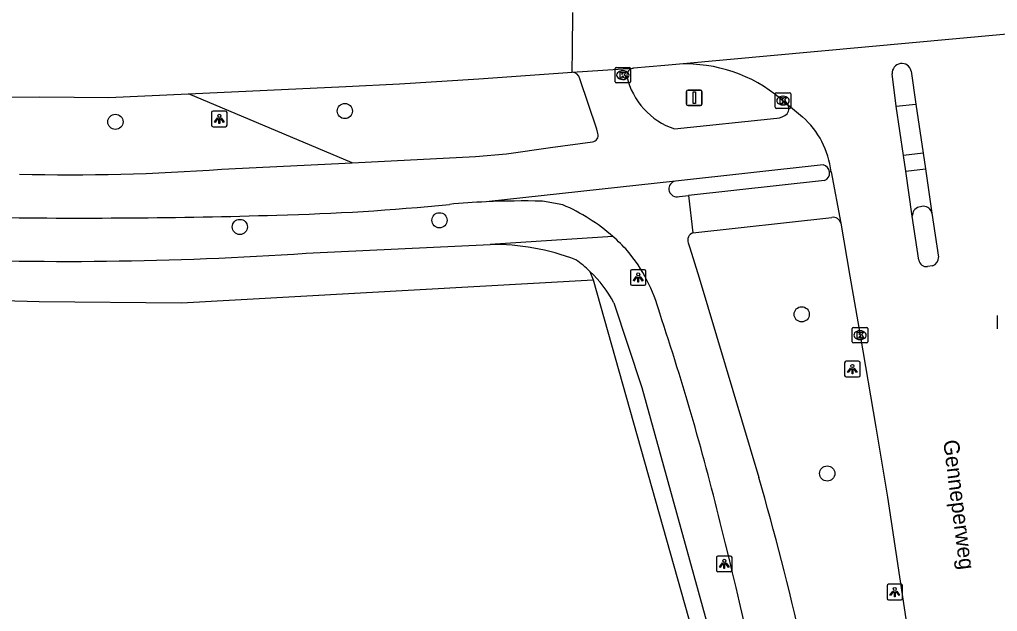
# Model space of a CAD drawing. Extents: x 160203 to 161526, y 379529 to 381797.
# Drawn here: x 160754.1 to 160816.9, y 380821.9 to 380859.9 of the extents above; entities that cross this region are included whole.
import ezdxf

# ---------------------------------------------------------------- set-up
doc = ezdxf.new("R2010")
doc.units = 0
for name, color, linetype in [('IMGEO_Berm_groen', 7, 'Continuous'), ('IMGEO_Boom', 7, 'Continuous'), ('IMGEO_Fietspad_open', 7, 'Continuous'), ('IMGEO_Grasland_agrarisch', 7, 'Continuous'), ('IMGEO_Hek', 7, 'Continuous'), ('IMGEO_Kolk', 7, 'Continuous'), ('IMGEO_Lichtpunt', 7, 'Continuous'), ('IMGEO_Openbare_ruimte_label', 7, 'Continuous'), ('IMGEO_Rijbaan_lokaal_gesloten', 7, 'Continuous'), ('IMGEO_Rijbaan_lokaal_open', 7, 'Continuous'), ('IMGEO_Verkeersbordpaal', 7, 'Continuous'), ('IMGEO_Voetpad_open', 7, 'Continuous')]:
    doc.layers.add(name, color=color, linetype=linetype)

msp = doc.modelspace()

# ---------------------------------------------------------------- linework, layer by layer
at = {"layer": 'IMGEO_Berm_groen'}
msp.add_lwpolyline([(160775.483, 380850.741), (160764.954, 380855.176)], dxfattribs=at)
at = {"layer": 'IMGEO_Boom'}
for centre in [(160775.008, 380854.065), (160760.26, 380853.371), (160768.259, 380846.611), (160781.086, 380847.039), (160804.366, 380840.994), (160806.008, 380830.763)]:
    msp.add_circle(centre, 0.489, dxfattribs=at)
at = {"layer": 'IMGEO_Fietspad_open'}
for points in [[(160791.275, 380852.614), (160791.205, 380852.905), (160790.104, 380856.13)], [(160810.441, 380854.37), (160811.699, 380854.505)], [(160796.186, 380852.912), (160802.764, 380853.61)], [(160775.483, 380850.741), (160783.41, 380851.131), (160785.393, 380851.307), (160788.226, 380851.722), (160790.924, 380852.076)], [(160812.162, 380851.362), (160810.902, 380851.209)], [(160767.104, 380850.329), (160775.483, 380850.741)], [(160805.738, 380850.598), (160796.255, 380849.562)], [(160806.25, 380850.156), (160806.159, 380850.144)]]:
    msp.add_lwpolyline(points, dxfattribs=at)
for centre, radius, start, end in [((160789.622, 380856.075), 0.485, 6.46696, 90.52993), ((160793.602, 380856.343), 0.479, 94.61403, 187.10993), ((160797.713, 380857.372), 4.715, 193.34725, 251.09856), ((160803.069, 380854.207), 0.478, 318.72664, 47.2899), ((160802.703, 380854.676), 1.068, 273.26806, 312.75369), ((160790.847, 380852.51), 0.44, 280.04651, 13.71132), ((160757.511, 380977.397), 127.43, 268.46675, 274.31751), ((160805.653, 380850.097), 0.508, 5.33471, 80.3456), ((160767.096, 380993.559), 146.229, 271.38388, 275.74179), ((160786.621, 380794.716), 53.571, 92.71443, 95.24266), ((160758.146, 381259.181), 411.998, 269.1062, 271.73614)]:
    msp.add_arc(centre, radius, start, end, dxfattribs=at)
at = {"layer": 'IMGEO_Grasland_agrarisch'}
msp.add_lwpolyline([(160790.757, 380843.757), (160790.967, 380843.218), (160797.794, 380818.979), (160800.72, 380802.882), (160803.667, 380782.861), (160807.097, 380750), (160808.197, 380741.734), (160810.001, 380733.144), (160811.746, 380725.723)], dxfattribs=at)
at = {"layer": 'IMGEO_Hek'}
msp.add_lwpolyline([(160724.662, 380842.651), (160726.668, 380842.596), (160727.305, 380842.579), (160755.37, 380841.813), (160764.499, 380841.725), (160790.967, 380843.218), (160797.794, 380818.979), (160800.72, 380802.882), (160803.667, 380782.861), (160807.097, 380750), (160808.197, 380741.734), (160810.001, 380733.144), (160811.746, 380725.723), (160812.287, 380716.603)], dxfattribs=at)
at = {"layer": 'IMGEO_Kolk'}
for p, q in [((160792.368, 380855.946), (160792.368, 380856.798)), ((160792.443, 380856.872), (160793.295, 380856.872)), ((160792.856, 380856.652), (160792.881, 380856.652)), ((160793.369, 380856.798), (160793.369, 380855.946)), ((160793.295, 380855.872), (160792.443, 380855.872)), ((160792.879, 380856.092), (160792.854, 380856.092)), ((160802.738, 380855.237), (160803.59, 380855.237)), ((160802.663, 380854.311), (160802.663, 380855.163)), ((160803.151, 380855.017), (160803.176, 380855.017)), ((160803.664, 380855.163), (160803.664, 380854.311)), ((160803.59, 380854.237), (160802.738, 380854.237)), ((160803.174, 380854.457), (160803.149, 380854.457)), ((160816.945, 380840.066), (160816.945, 380840.918)), ((160807.691, 380840.153), (160808.543, 380840.153)), ((160807.616, 380839.227), (160807.616, 380840.079)), ((160808.104, 380839.933), (160808.129, 380839.933)), ((160808.617, 380840.079), (160808.617, 380839.227)), ((160808.543, 380839.153), (160807.691, 380839.153)), ((160808.127, 380839.373), (160808.102, 380839.373))]:
    msp.add_line(p, q, dxfattribs=at)
for points in [[(160792.368, 380855.946), (160792.368, 380856.798)], [(160792.443, 380856.872), (160793.295, 380856.872)], [(160792.689, 380856.572), (160792.812, 380856.572), (160792.812, 380856.421), (160792.942, 380856.572), (160793.106, 380856.572), (160792.96, 380856.421), (160793.113, 380856.172), (160792.961, 380856.172), (160792.876, 380856.336), (160792.812, 380856.269), (160792.812, 380856.172), (160792.689, 380856.172), (160792.689, 380856.572)], [(160793.369, 380856.798), (160793.369, 380855.946)], [(160793.295, 380855.872), (160792.443, 380855.872)], [(160802.738, 380855.237), (160803.59, 380855.237)], [(160802.663, 380854.311), (160802.663, 380855.163)], [(160802.984, 380854.937), (160803.107, 380854.937), (160803.107, 380854.786), (160803.237, 380854.937), (160803.401, 380854.937), (160803.255, 380854.786), (160803.408, 380854.537), (160803.256, 380854.537), (160803.171, 380854.701), (160803.107, 380854.634), (160803.107, 380854.537), (160802.984, 380854.537), (160802.984, 380854.937)], [(160803.664, 380855.163), (160803.664, 380854.311)], [(160803.59, 380854.237), (160802.738, 380854.237)], [(160816.945, 380840.066), (160816.945, 380840.918)], [(160807.691, 380840.153), (160808.543, 380840.153)], [(160807.616, 380839.227), (160807.616, 380840.079)], [(160807.937, 380839.853), (160808.06, 380839.853), (160808.06, 380839.702), (160808.19, 380839.853), (160808.354, 380839.853), (160808.208, 380839.702), (160808.361, 380839.453), (160808.209, 380839.453), (160808.124, 380839.617), (160808.06, 380839.55), (160808.06, 380839.453), (160807.937, 380839.453), (160807.937, 380839.853)], [(160808.617, 380840.079), (160808.617, 380839.227)], [(160808.543, 380839.153), (160807.691, 380839.153)]]:
    msp.add_lwpolyline(points, dxfattribs=at)
for centre, start, end in [((160792.445, 380856.796), 91.55205, 178.44795), ((160792.445, 380856.796), 91.55205, 178.44795), ((160793.293, 380856.796), 1.55205, 88.44795), ((160793.293, 380856.796), 1.55205, 88.44795), ((160792.445, 380855.948), 181.55205, 268.44795), ((160792.445, 380855.948), 181.55205, 268.44795), ((160793.293, 380855.948), 271.55205, 358.44795), ((160793.293, 380855.948), 271.55205, 358.44795), ((160802.74, 380855.161), 91.55205, 178.44795), ((160802.74, 380855.161), 91.55205, 178.44795), ((160803.588, 380855.161), 1.55205, 88.44795), ((160803.588, 380855.161), 1.55205, 88.44795), ((160802.74, 380854.313), 181.55205, 268.44795), ((160802.74, 380854.313), 181.55205, 268.44795), ((160803.588, 380854.313), 271.55205, 358.44795), ((160803.588, 380854.313), 271.55205, 358.44795), ((160807.693, 380840.077), 91.55205, 178.44795), ((160807.693, 380840.077), 91.55205, 178.44795), ((160808.541, 380840.077), 1.55205, 88.44795), ((160808.541, 380840.077), 1.55205, 88.44795), ((160807.693, 380839.229), 181.55205, 268.44795), ((160807.693, 380839.229), 181.55205, 268.44795), ((160808.541, 380839.229), 271.55205, 358.44795), ((160808.541, 380839.229), 271.55205, 358.44795)]:
    msp.add_arc(centre, 0.0765, start, end, dxfattribs=at)
for centre, major_axis, ratio, start_param, end_param in [((160792.855, 380856.372), (-0.387, 0.002), 0.722429, 4.712389, 7.853982), ((160792.88, 380856.372), (-0.39, 0.002), 0.717154, 1.570796, 4.712389), ((160803.15, 380854.737), (-0.387, 0.002), 0.722429, 4.712389, 7.853982), ((160803.175, 380854.737), (-0.39, 0.002), 0.717154, 1.570796, 4.712389), ((160808.103, 380839.653), (-0.387, 0.002), 0.722429, 4.712389, 7.853982), ((160808.128, 380839.653), (-0.39, 0.002), 0.717154, 1.570796, 4.712389)]:
    msp.add_ellipse(centre, major_axis=major_axis, ratio=ratio, start_param=start_param, end_param=end_param, dxfattribs=at)
at = {"layer": 'IMGEO_Lichtpunt'}
for p, q in [((160766.44, 380853.959), (160766.44, 380853.152)), ((160766.44, 380853.959), (160766.44, 380853.152)), ((160767.342, 380854.054), (160766.534, 380854.054)), ((160767.342, 380854.054), (160766.534, 380854.054)), ((160767.436, 380853.152), (160767.436, 380853.959)), ((160767.436, 380853.152), (160767.436, 380853.959)), ((160766.534, 380853.058), (160767.342, 380853.058)), ((160766.534, 380853.058), (160767.342, 380853.058)), ((160793.362, 380843.762), (160793.362, 380842.955)), ((160793.362, 380843.762), (160793.362, 380842.955)), ((160794.264, 380843.857), (160793.456, 380843.857)), ((160794.264, 380843.857), (160793.456, 380843.857)), ((160794.358, 380842.955), (160794.358, 380843.762)), ((160794.358, 380842.955), (160794.358, 380843.762)), ((160793.456, 380842.861), (160794.264, 380842.861)), ((160793.456, 380842.861), (160794.264, 380842.861)), ((160807.124, 380837.877), (160807.124, 380837.07)), ((160807.124, 380837.877), (160807.124, 380837.07)), ((160808.026, 380837.972), (160807.218, 380837.972)), ((160808.026, 380837.972), (160807.218, 380837.972)), ((160808.12, 380837.07), (160808.12, 380837.877)), ((160808.12, 380837.07), (160808.12, 380837.877)), ((160807.218, 380836.976), (160808.026, 380836.976)), ((160807.218, 380836.976), (160808.026, 380836.976)), ((160798.892, 380825.35), (160798.892, 380824.543)), ((160798.892, 380825.35), (160798.892, 380824.543)), ((160799.794, 380825.445), (160798.986, 380825.445)), ((160799.794, 380825.445), (160798.986, 380825.445)), ((160799.888, 380824.543), (160799.888, 380825.35)), ((160799.888, 380824.543), (160799.888, 380825.35)), ((160798.986, 380824.449), (160799.794, 380824.449)), ((160798.986, 380824.449), (160799.794, 380824.449)), ((160809.849, 380823.541), (160809.849, 380822.734)), ((160809.849, 380823.541), (160809.849, 380822.734)), ((160810.751, 380823.636), (160809.943, 380823.636)), ((160810.751, 380823.636), (160809.943, 380823.636)), ((160810.845, 380822.734), (160810.845, 380823.541)), ((160810.845, 380822.734), (160810.845, 380823.541)), ((160809.943, 380822.64), (160810.751, 380822.64)), ((160809.943, 380822.64), (160810.751, 380822.64))]:
    msp.add_line(p, q, dxfattribs=at)
for points in [[(160766.814, 380853.623), (160766.853, 380853.595), (160766.665, 380853.333), (160766.627, 380853.36), (160766.814, 380853.623)], [(160766.916, 380853.575), (160766.963, 380853.575), (160766.963, 380853.253), (160766.916, 380853.253), (160766.916, 380853.575)], [(160767.026, 380853.595), (160767.064, 380853.622), (160767.251, 380853.36), (160767.212, 380853.332), (160767.026, 380853.595)], [(160793.736, 380843.426), (160793.775, 380843.398), (160793.587, 380843.136), (160793.549, 380843.163), (160793.736, 380843.426)], [(160793.838, 380843.378), (160793.885, 380843.378), (160793.885, 380843.056), (160793.838, 380843.056), (160793.838, 380843.378)], [(160793.948, 380843.398), (160793.986, 380843.425), (160794.173, 380843.163), (160794.134, 380843.135), (160793.948, 380843.398)], [(160807.498, 380837.541), (160807.537, 380837.513), (160807.349, 380837.251), (160807.311, 380837.278), (160807.498, 380837.541)], [(160807.6, 380837.493), (160807.647, 380837.493), (160807.647, 380837.171), (160807.6, 380837.171), (160807.6, 380837.493)], [(160807.71, 380837.513), (160807.748, 380837.54), (160807.935, 380837.278), (160807.896, 380837.25), (160807.71, 380837.513)], [(160799.266, 380825.014), (160799.305, 380824.986), (160799.117, 380824.724), (160799.079, 380824.751), (160799.266, 380825.014)], [(160799.368, 380824.966), (160799.415, 380824.966), (160799.415, 380824.644), (160799.368, 380824.644), (160799.368, 380824.966)], [(160799.478, 380824.986), (160799.516, 380825.013), (160799.703, 380824.751), (160799.664, 380824.723), (160799.478, 380824.986)], [(160810.223, 380823.205), (160810.262, 380823.177), (160810.074, 380822.915), (160810.036, 380822.942), (160810.223, 380823.205)], [(160810.325, 380823.157), (160810.372, 380823.157), (160810.372, 380822.835), (160810.325, 380822.835), (160810.325, 380823.157)], [(160810.435, 380823.177), (160810.473, 380823.204), (160810.66, 380822.942), (160810.621, 380822.914), (160810.435, 380823.177)]]:
    msp.add_lwpolyline(points, dxfattribs=at)
for centre in [(160766.939, 380853.757), (160793.861, 380843.56), (160807.623, 380837.675), (160799.391, 380825.148), (160810.348, 380823.339)]:
    msp.add_circle(centre, 0.0994, dxfattribs=at)
for centre, start, end in [((160766.534, 380853.959), 90, 180), ((160766.534, 380853.959), 90, 180), ((160767.342, 380853.959), 0, 90), ((160767.342, 380853.959), 0, 90), ((160766.534, 380853.152), 180, 270), ((160766.534, 380853.152), 180, 270), ((160767.342, 380853.152), 270, 0), ((160767.342, 380853.152), 270, 360), ((160793.456, 380843.762), 90, 180), ((160793.456, 380843.762), 90, 180), ((160794.264, 380843.762), 0, 90), ((160794.264, 380843.762), 0, 90), ((160793.456, 380842.955), 180, 270), ((160793.456, 380842.955), 180, 270), ((160794.264, 380842.955), 270, 0), ((160794.264, 380842.955), 270, 360), ((160807.218, 380837.877), 90, 180), ((160807.218, 380837.877), 90, 180), ((160808.026, 380837.877), 0, 90), ((160808.026, 380837.877), 0, 90), ((160807.218, 380837.07), 180, 270), ((160807.218, 380837.07), 180, 270), ((160808.026, 380837.07), 270, 0), ((160808.026, 380837.07), 270, 360), ((160798.986, 380825.35), 90, 180), ((160798.986, 380825.35), 90, 180), ((160799.794, 380825.35), 0, 90), ((160799.794, 380825.35), 0, 90), ((160798.986, 380824.543), 180, 270), ((160798.986, 380824.543), 180, 270), ((160799.794, 380824.543), 270, 0), ((160799.794, 380824.543), 270, 360), ((160809.943, 380823.541), 90, 180), ((160809.943, 380823.541), 90, 180), ((160810.751, 380823.541), 0, 90), ((160810.751, 380823.541), 0, 90), ((160809.943, 380822.734), 180, 270), ((160809.943, 380822.734), 180, 270), ((160810.751, 380822.734), 270, 0), ((160810.751, 380822.734), 270, 360)]:
    msp.add_arc(centre, 0.0946, start, end, dxfattribs=at)
at = {"layer": 'IMGEO_Rijbaan_lokaal_gesloten'}
for points in [[(160789.618, 380856.56), (160789.635, 380858.023), (160789.663, 380860.405)], [(160826.217, 380859.799), (160796.504, 380857.081)], [(160764.954, 380855.176), (160775.062, 380855.643), (160778.519, 380855.813), (160783.616, 380856.141), (160789.618, 380856.56)], [(160789.618, 380856.56), (160793.563, 380856.821)], [(160796.504, 380857.081), (160795.573, 380856.996), (160793.563, 380856.821)], [(160811.402, 380856.634), (160811.699, 380854.505)], [(160810.441, 380854.37), (160810.186, 380856.454)], [(160744.138, 380854.84), (160755.396, 380854.972), (160759.808, 380854.938), (160764.954, 380855.176)], [(160802.987, 380854.879), (160803.164, 380854.737), (160803.393, 380854.558)], [(160803.393, 380854.558), (160804.422, 380853.693)], [(160810.902, 380851.209), (160810.441, 380854.37)], [(160811.699, 380854.505), (160812.162, 380851.362)], [(160811.051, 380850.192), (160810.902, 380851.209)], [(160812.162, 380851.362), (160812.313, 380850.338)], [(160811.474, 380847.299), (160811.051, 380850.192)], [(160812.313, 380850.338), (160812.732, 380847.498)], [(160806.25, 380850.156), (160806.873, 380846.856)], [(160811.898, 380844.476), (160811.474, 380847.299)], [(160812.732, 380847.498), (160813.156, 380844.658)], [(160806.873, 380846.856), (160807.466, 380843.452), (160808.117, 380839.653), (160809.121, 380833.749), (160809.889, 380829.228), (160811.188, 380820.562), (160811.35, 380819.337), (160811.402, 380819.029), (160811.548, 380817.956), (160811.638, 380817.24), (160811.727, 380816.523)], [(160812.775, 380844.11), (160812.454, 380844.07)]]:
    msp.add_lwpolyline(points, dxfattribs=at)
for centre, radius, start, end in [((160796.902, 380847.608), 9.481, 50.07425, 92.40486), ((160810.8, 380856.506), 0.616, 12.00819, 184.83208), ((160800.762, 380849.561), 5.52, 6.1927, 48.46915), ((160812.605, 380844.634), 0.551, 287.93711, 2.44456), ((160812.382, 380844.555), 0.491, 189.30928, 278.4157)]:
    msp.add_arc(centre, radius, start, end, dxfattribs=at)
at = {"layer": 'IMGEO_Rijbaan_lokaal_open'}
for points in [[(160796.255, 380849.562), (160784.084, 380848.227)], [(160796.379, 380848.556), (160796.51, 380848.57), (160797.095, 380848.635)], [(160797.095, 380848.635), (160797.364, 380846.226)], [(160789.02, 380848.033), (160787.699, 380848.266)], [(160797.078, 380845.588), (160797.174, 380845.259), (160797.767, 380843.337), (160801.609, 380830.509)]]:
    msp.add_lwpolyline(points, dxfattribs=at)
for centre, radius, start, end in [((160796.334, 380849.061), 0.507, 98.99502, 275.0587), ((160786.447, 380796.744), 51.538, 88.60813, 92.62808), ((160784.236, 380836.928), 12.091, 48.57084, 66.69445), ((160784.148, 380836.844), 12.213, 42.41548, 48.51918), ((160797.537, 380845.766), 0.492, 110.54587, 201.16305), ((160785.216, 380838.43), 10.364, 14.73719, 39.92373), ((160637.196, 380788.083), 166.688, 13.56515, 18.53369), ((160601.801, 380773.217), 207.86, 9.89275, 15.99952), ((160459.279, 380742.383), 350.371, 8.96171, 14.0058)]:
    msp.add_arc(centre, radius, start, end, dxfattribs=at)
at = {"layer": 'IMGEO_Verkeersbordpaal'}
for p, q in [((160796.962, 380854.514), (160796.962, 380855.314)), ((160796.962, 380855.314), (160796.962, 380854.514)), ((160797.062, 380855.414), (160797.852, 380855.414)), ((160797.852, 380855.414), (160797.062, 380855.414)), ((160797.952, 380855.314), (160797.952, 380854.514)), ((160797.952, 380854.514), (160797.952, 380855.314)), ((160797.852, 380854.414), (160797.062, 380854.414)), ((160797.062, 380854.414), (160797.852, 380854.414))]:
    msp.add_line(p, q, dxfattribs=at)
msp.add_lwpolyline([(160797.382, 380855.289), (160797.532, 380855.289), (160797.532, 380854.539), (160797.382, 380854.539), (160797.382, 380855.289)], dxfattribs=at)
for centre, start, end in [((160797.062, 380855.314), 90, 180), ((160797.062, 380855.314), 90, 180), ((160797.852, 380855.314), 0, 90), ((160797.852, 380855.314), 360, 90), ((160797.062, 380854.514), 180, 270), ((160797.062, 380854.514), 180, 270), ((160797.852, 380854.514), 270, 0), ((160797.852, 380854.514), 270, 0)]:
    msp.add_arc(centre, 0.1, start, end, dxfattribs=at)
at = {"layer": 'IMGEO_Voetpad_open'}
for points in [[(160811.051, 380850.192), (160812.313, 380850.338)], [(160805.822, 380849.603), (160797.095, 380848.635)], [(160812.192, 380847.941), (160811.895, 380847.888)], [(160797.364, 380846.226), (160806.313, 380847.227)], [(160792.237, 380845.994), (160784.342, 380845.483)], [(160772.526, 380844.917), (160784.342, 380845.483)], [(160792.287, 380841.731), (160794.091, 380836.288), (160798.819, 380819.176)]]:
    msp.add_lwpolyline(points, dxfattribs=at)
for centre, radius, start, end in [((160805.664, 380850.077), 0.5, 288.47712, 7.68363), ((160812.061, 380847.324), 0.588, 106.4188, 182.46905), ((160812.203, 380847.404), 0.537, 10.10763, 91.16349), ((160806.404, 380846.757), 0.479, 11.97021, 100.98085), ((160784.563, 380830.809), 14.675, 68.88103, 90.86459), ((160757.056, 381074.743), 230.346, 267.46117, 273.85099), ((160785.379, 380838.114), 7.795, 46.37516, 54.99095), ((160785.315, 380838.057), 7.881, 27.79043, 46.32851)]:
    msp.add_arc(centre, radius, start, end, dxfattribs=at)

# ---------------------------------------------------------------- texts
at = {"layer": 'IMGEO_Openbare_ruimte_label'}
msp.add_text('Genneperweg', height=1, rotation=277.23873, dxfattribs=at).set_placement((160813.456, 380832.866))

doc.saveas('drawing.dxf')
